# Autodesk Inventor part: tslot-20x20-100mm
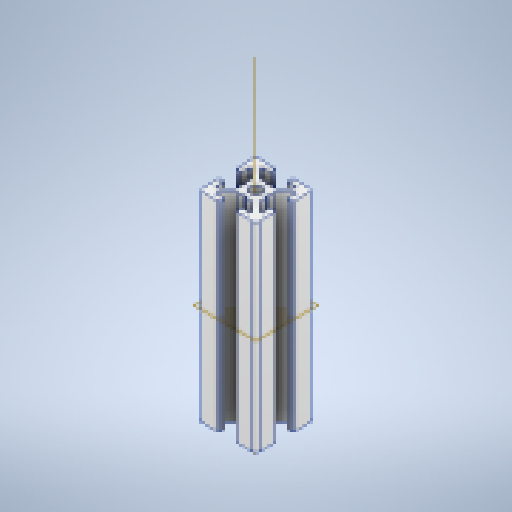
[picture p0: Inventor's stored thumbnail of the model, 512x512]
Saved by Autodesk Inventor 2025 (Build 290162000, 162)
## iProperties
Created: 2025-03
Part Number: tslot-20x20-100mm
Material: Alluminio 6061
Document SubType Name: Modeling
Designer: Ryzen5700u
Density: 2.7 g/cm^3
Appearance: Alluminio - Piatto
Author: Ryzen5700u
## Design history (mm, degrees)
feature "Base1"
sketch "Schizzo1"
  geometry: L1 (3.761, -16)-(4.7, -16) reference; L2 (3.761, -16)-(0.7, -12.939) reference; L3 (0.7, -12.939)-(0.7, -10.52) reference; L4 (0.4, -10)-(0.7, -10.52) reference; L5 (0.4, -10)-(0.7, -9.48) reference; L6 (0.7, -7.061)-(0.7, -9.48) reference; L7 (3.761, -4)-(0.7, -7.061) reference; L8 (3.761, -4)-(4.7, -4) reference; L9 (4.7, -4)-(4.7, -7) reference; L10 (4.7, -7)-(6.4, -7) reference; L11 (6.7, -6.7)-(6.7, -1) reference; L12 (5.7, 0)-(0, 0) reference; L13 (-0.3, -2)-(-0.3, -0.3) reference; L14 (2.7, -2)-(-0.3, -2) reference; L15 (2.7, -2.939)-(2.7, -2) reference; L16 (2.7, -2.939)-(-0.361, -6) reference; L17 (-0.361, -6)-(-2.78, -6) reference; L18 (-3.3, -6.3)-(-2.78, -6) reference; L19 (-3.3, -6.3)-(-3.82, -6) reference; L20 (-6.239, -6)-(-3.82, -6) reference; L21 (-9.3, -2.939)-(-6.239, -6) reference; L22 (-9.3, -2.939)-(-9.3, -2) reference; L23 (-9.3, -2)-(-6.3, -2) reference; L24 (-6.3, -2)-(-6.3, -0.3) reference; L25 (-12.3, 0)-(-6.6, 0) reference; L26 (-13.3, -6.7)-(-13.3, -1) reference; L27 (-11.3, -7)-(-13, -7) reference; L28 (-11.3, -4)-(-11.3, -7) reference; L29 (-10.361, -4)-(-11.3, -4) reference; L30 (-10.361, -4)-(-7.3, -7.061) reference; L31 (-7.3, -7.061)-(-7.3, -9.48) reference; L32 (-7, -10)-(-7.3, -9.48) reference; L33 (-7, -10)-(-7.3, -10.52) reference; L34 (-7.3, -12.939)-(-7.3, -10.52) reference; L35 (-10.361, -16)-(-7.3, -12.939) reference; L36 (-10.361, -16)-(-11.3, -16) reference; L37 (-11.3, -16)-(-11.3, -13) reference; L38 (-11.3, -13)-(-13, -13) reference; L39 (-13.3, -13.3)-(-13.3, -19) reference; L40 (-12.3, -20)-(-6.6, -20) reference; L41 (-6.3, -18)-(-6.3, -19.7) reference; L42 (-9.3, -18)-(-6.3, -18) reference; L43 (-9.3, -17.061)-(-9.3, -18) reference; L44 (-9.3, -17.061)-(-6.239, -14) reference; L45 (-6.239, -14)-(-3.82, -14) reference; L46 (-3.3, -13.7)-(-3.82, -14) reference; L47 (-3.3, -13.7)-(-2.78, -14) reference; L48 (-0.361, -14)-(-2.78, -14) reference; L49 (2.7, -17.061)-(-0.361, -14) reference; L50 (2.7, -17.061)-(2.7, -18) reference; L51 (2.7, -18)-(-0.3, -18) reference; L52 (-0.3, -18)-(-0.3, -19.7) reference; L53 (5.7, -20)-(0, -20) reference; L54 (6.7, -13.3)-(6.7, -19) reference; L55 (4.7, -13)-(6.4, -13) reference; L56 (4.7, -16)-(4.7, -13) reference; C1 r 2.1 at (-3.3, -10) reference; A1 r 0.3 centre (6.4, -6.7) between (6.4, -7) and (6.7, -6.7) reference; A2 r 1 centre (5.7, -1) between (6.7, -1) and (5.7, 0) reference; A3 r 0.3 centre (0, -0.3) between (0, 0) and (-0.3, -0.3) reference; A4 r 0.3 centre (-6.6, -0.3) between (-6.3, -0.3) and (-6.6, 0) reference; A5 r 1 centre (-12.3, -1) between (-12.3, 0) and (-13.3, -1) reference; A6 r 0.3 centre (-13, -6.7) between (-13.3, -6.7) and (-13, -7) reference; A7 r 0.3 centre (-13, -13.3) between (-13, -13) and (-13.3, -13.3) reference; A8 r 1 centre (-12.3, -19) between (-13.3, -19) and (-12.3, -20) reference; A9 r 0.3 centre (-6.6, -19.7) between (-6.6, -20) and (-6.3, -19.7) reference; A10 r 0.3 centre (0, -19.7) between (-0.3, -19.7) and (0, -20) reference; A11 r 1 centre (5.7, -19) between (5.7, -20) and (6.7, -19) reference; A12 r 0.3 centre (6.4, -13.3) between (6.7, -13.3) and (6.4, -13) reference; 1 further point
extrude "Estrusione1" join sketch "Schizzo1" distance "d0" = 80; taper "d1" = 0 deg
node "Piano di lavoro1"
node "Asse di lavoro1"
node "Solido1"
node "Linea chiusa proiettata1"
